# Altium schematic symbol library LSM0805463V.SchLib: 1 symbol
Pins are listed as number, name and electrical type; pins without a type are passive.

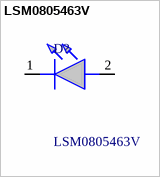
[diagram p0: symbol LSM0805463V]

## LSM0805463V
designator D?
Standard LEDs - SMD 0805 3V 100mcd Blue; Manufacturer_Name: Visual Communications Company; Geometry.Height: 0.9mm
footprint LEDC2012X90N
pins: 1 K, 2 A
